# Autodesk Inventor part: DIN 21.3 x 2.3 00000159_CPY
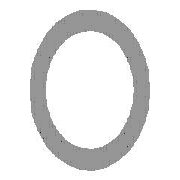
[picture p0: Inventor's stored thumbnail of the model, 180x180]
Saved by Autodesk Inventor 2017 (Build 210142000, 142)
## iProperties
Created: 2016-02
Part Number: DIN 21.3 x 2.3 00000159_CPY
Material: Steel, Mild
Description: Pipe
Document SubType Name: Modeling
Standard: DIN
Designer: iusti
Standard Revision: 2006-07
Standards Organization: DIN
Language: en-US
Size Designation: 21.3 x 2.3
Categories: <MemberInstance><Categories><Category DisplayName="Structural Shapes" InternalName="089c4875-fa83-4c05-b084-43b9cc11f5ed" Mnemonic="GRDR"><CategoryParameter Dis
Stock Number: 21.3 x 2.3
Density: 7.85 g/cm^3
Appearance: Semi-Polished
IsCustomPart: 1
G_L: 5240.313 mm
G_W: 21.300 mm
G_H: 21.300 mm
_CCFamilyMember: 1
_CCFamilyDisplayName: DIN EN 10210-2 - Pipe
_FrameMemberDoc: Frame Member File
_Version: 15.0.0
_GetPNFromCC: 1
Author: iusti
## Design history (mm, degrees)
node "Start plane"
node "End plane"
sketch "Sketch"
  geometry: C1 r 8.35 at (0, 0); C2 r 10.65 at (0, 0); 2 further points
  constraints: 3 coincident, 2 centre point
  dimensions: "d0" = 21.3 diameter of C2 (= G_H); "d1" = 2.3 radial gap between concentric circles of C2 C1 (= G_T)
extrude "Body" new body sketch "Sketch" stored distance "d2" = 5240.31264 (= G_L); taper "d3" = 0 deg
node "Driven Length"
  sketch "Sketch3"
    geometry: L1 (0, 0)-(10, 0) reference
    constraints: 2 end point, 1 horizontal
  workplane "Work Plane3"
  sketch "Sketch4"
    geometry: L1 (-2, 0)-(12, 0) reference; L2 (-2, 5240.313)-(12, 5240.313) reference
    dimensions: "d7" = 5240.31264 distance between parallel lines of L1 L2 (derived)
body "Solid1"
other parameters: "G_H" = 21.3 [user parameter; used in 1 equation term], "G_T" = 2.3 [user parameter; used in 1 equation term], "G_L" = 5240.31264 (= d7) [user parameter; used in 1 equation term], "G_OFFSET_START" = 0 [user parameter; used in 1 equation term], "G_OFFSET_END" = 0 [user parameter; used in 1 equation term], "d4" = 0 (computed from G_OFFSET_START), "d5" = 5240.31264 (= G_OFFSET_END + B_L), "B_L" = 5240.31264 [user parameter; used in 1 equation term], "d6" = 90 deg
